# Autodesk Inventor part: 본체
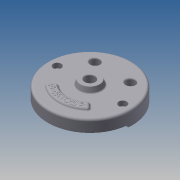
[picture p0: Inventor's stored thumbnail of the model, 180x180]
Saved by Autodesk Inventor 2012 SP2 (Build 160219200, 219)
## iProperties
Created: 2015-05
Part Number: 본체
Material: 알루미늄-6061
Document SubType Name: Modeling
Designer: Administrator
Density: 2.71 g/cm^3
Mass: 1082.43 g
Surface Area: 1039.74 cm^2
Volume: 399.421 cm^3
Author: Administrator
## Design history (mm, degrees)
sketch "스케치1"
  geometry: C1 r 95 at (0, 0); 1 further point
  constraints: 1 centre point, 1 coincident
  dimensions: "d0" = 190 diameter of C1
extrude "돌출1" new body sketch "스케치1" distance "d1" = 32; taper "d2" = 0 deg
sketch "스케치2"
  geometry: C1 r 95 at (0, 0) reference; C2 r 25 at (0, 0)
  constraints: 1 centre point, 1 coincident
  dimensions: "d3" = 50 diameter of C2
extrude "돌출2" join sketch "스케치2" distance "d4" = 12; taper "d5" = 0 deg
sketch "스케치3"
  geometry: L1 (0, 0)-(0, 49.604); L2 (-25, 32)-(-25, 44) reference; L3 (-25, 44)-(25, 44) reference; L4 (-25, 32)-(-21.785, 44); L5 (-95, 32)-(95, 32) reference
  constraints: 4 end point, 1 point on line, 1 vertical
  dimensions: "d6" = 105 deg angle of L5 L4
revolve "회전1" sketch "스케치3" stored, may be unused: angle "d7" = 90 deg
sketch "스케치4"
  geometry: L1 (0, 0)-(-94.638, -8.28); L2 (0, 0)-(94.638, -8.28); L3 (0, 0)-(-95, 0); L4 (0, 0)-(95, 0); A1 r 95 centre (0, 0) between (-94.638, -8.28) and (94.638, -8.28) reference
  constraints: 8 end point, 4 point on circle, 1 collinear, 1 horizontal
  dimensions: "d8" = 5 deg angle of L1 L3; "d9" = 5 deg angle of L2 L4
extrude "돌출3" cut sketch "스케치4" distance "d10" = 5; taper "d11" = 0 deg
sketch "스케치5"
  geometry: L1 (-89.196, 12)-(-40.249, 12); L2 (40.249, 12)-(89.196, 12); A1 r 95 centre (0, 0) between (94.638, -8.28) and (-94.638, -8.28) reference; A2 r 90 centre (0, 0) between (89.196, 12) and (-89.196, 12); A3 r 42 centre (0, 0) between (40.249, 12) and (-40.249, 12); 1 further point
  constraints: 4 end point, 4 point on circle, 2 centre point, 2 coincident, 2 horizontal, 1 collinear
  dimensions: "d12" = 180 diameter of A2; "d14" = 84 diameter of A3; "d15" = 12 distance from line of L1 point (0, 0)
extrude "돌출4" cut sketch "스케치5" distance "d16" = 25; taper "d17" = 0 deg
sketch "스케치6"
  geometry: L1 (-40.249, 12)-(-89.196, 12) reference; L2 (89.196, 12)-(40.249, 12) reference; L3 (-89.196, 12)-(-40.249, 12); L4 (89.196, 12)-(40.249, 12); A1 r 95 centre (0, 0) between (94.638, -8.28) and (-94.638, -8.28) reference; A2 r 90 centre (0, 0) between (-89.196, 12) and (89.196, 12); A3 r 42 centre (0, 0) between (40.249, 12) and (-40.249, 12)
  constraints: 4 end point, 4 point on circle, 2 centre point, 2 coincident, 2 collinear
extrude "돌출5" cut sketch "스케치6" distance "d19" = 18; taper "d20" = 0 deg
sketch "스케치7"
  geometry: C1 r 35 at (0, 0); A1 r 42 centre (0, 0) between (40.249, 12) and (-40.249, 12) reference
  constraints: 1 centre point, 1 coincident
  dimensions: "d21" = 70 diameter of C1
extrude "돌출6" join sketch "스케치7" distance "d22" = 10; taper "d23" = 0 deg
sketch "스케치8"
  geometry: L1 (-89.196, 12)-(-40.249, 12) reference; L2 (-59, -19)-(59, -19); L3 (-59, -19)-(-59, -14); L4 (-41, -19)-(-41, -14); L5 (41, -19)-(41, -14); L6 (59, -19)-(59, -14); C1 r 35 at (0, 0) reference; A1 r 59 centre (0, -19) between (-59, -19) and (59, -19); A2 r 41 centre (0, -19) between (-41, -19) and (41, -19); A3 r 9 centre (-50, -14) between (-41, -14) and (-59, -14); A4 r 9 centre (50, -14) between (59, -14) and (41, -14); 1 further point
  constraints: 10 end point, 8 point on circle, 8 tangent, 7 parallel, 4 centre point, 2 coincident, 2 point on line, 1 midpoint, 1 perpendicular, 1 vertical alignment
  dimensions: "d24" = 118 diameter of A1; "d25" = 19 distance of A1.centre C1.centre; "d26" = 82 diameter of A2; "d27" = 5 distance of L2.start L3.end
extrude "돌출7" cut sketch "스케치8" distance "d28" = 7; taper "d29" = 0 deg
chamfer "모따기1" distance "d30" = 1; stored, may be unused: second distance "d31" = 2, angle "d32" = 45 deg
sketch "스케치9"
  geometry: C1 r 35 at (0, 0) reference; C2 r 25 at (0, 0)
  constraints: 1 centre point, 1 coincident
  dimensions: "d33" = 50 diameter of C2
extrude "돌출8" cut sketch "스케치9" distance "d34" = 15; taper "d35" = 0 deg
sketch "스케치10"
  geometry: C1 r 25 at (0, 0) reference; C2 r 11.5 at (0, 0)
  constraints: 1 centre point, 1 coincident
  dimensions: "d36" = 23 diameter of C2
extrude "돌출9" cut sketch "스케치10" stored distance "d37" = 15; taper "d38" = 0 deg
chamfer "모따기2" distance "d39" = 1; stored, may be unused: second distance "d40" = 2, angle "d41" = 45 deg
chamfer "모따기3" distance "d42" = 1; stored, may be unused: second distance "d43" = 2, angle "d44" = 45 deg
fillet "모깎기1" dims "d45" = 10
sketch "스케치11"
  geometry: L1 (35, 8)-(-35, 8) reference; L2 (35, 18)-(35, 8) reference; L3 (35, 18)-(33.237, 8); L4 (42, 18)-(17.769, 18) reference; L5 (0, -8.8)-(0, 52.8) reference; 1 further point
  constraints: 2 end point, 1 point on line
  dimensions: "d46" = 100 deg angle of L4 L3
revolve "회전2" sketch "스케치11" stored, may be unused: angle "d47" = 90 deg
sketch "스케치12"
  geometry: C1 r 15 at (-40, 52); C2 r 15 at (40, 52); C3 r 95 at (0, 0) reference; A1 r 90 centre (0, 0) between (86.53, 24.75) and (-86.53, 24.75) reference
  constraints: 2 centre point, 1 horizontal alignment
  dimensions: "d48" = 30 diameter of C1; "d49" = 30 diameter of C2; "d51" = 80 distance of C2.centre C1.centre; "d52" = 52 vertical distance of C1.centre A1.centre; "d53" = 40 horizontal distance of C3.centre C1.centre
extrude "돌출10" join sketch "스케치12" distance "d54" = 25; taper "d55" = 0 deg
hole "구멍1" diameter "d58" = 20; stored, may be unused: countersink angle "d62" = 90 deg, drill point angle "d64" = 118 deg; dims "d56" = 10, "d57" = 10, "d59" = 6, "d60" = 4, "d61" = 2, "d63" = 8
hole "구멍2" diameter "d67" = 20; stored, may be unused: countersink angle "d71" = 90 deg, drill point angle "d73" = 118 deg; dims "d65" = 10, "d66" = 10, "d68" = 6, "d69" = 4, "d70" = 2, "d72" = 8
sketch "스케치13"
  geometry: C1 r 9 at (-74, 0); C2 r 9 at (74, 0); A1 r 90 centre (0, 0) between (-86.53, 24.75) and (86.53, 24.75) reference
  constraints: 2 centre point, 2 horizontal alignment
  dimensions: "d74" = 18 diameter of C1; "d75" = 18 diameter of C2; "d76" = 74 distance of C1.centre A1.centre; "d77" = 148 distance of C2.centre C1.centre
extrude "돌출11" join sketch "스케치13" distance "d78" = 18; taper "d79" = 0 deg
hole "구멍3" diameter "d82" = 11; stored, may be unused: countersink angle "d86" = 90 deg, drill point angle "d88" = 118 deg; dims "d80" = 10, "d81" = 10, "d83" = 6, "d84" = 4, "d85" = 2, "d87" = 8
hole "구멍4" diameter "d91" = 11; stored, may be unused: countersink angle "d95" = 90 deg, drill point angle "d97" = 118 deg; dims "d89" = 10, "d90" = 10, "d92" = 6, "d93" = 4, "d94" = 2, "d96" = 8
sketch "스케치14"
  geometry: C1 r 5.5 at (-74, 0) reference; C2 r 5.5 at (74, 0) reference; C3 r 9 at (-74, 0); C4 r 9 at (74, 0)
  constraints: 2 centre point, 2 coincident
  dimensions: "d98" = 18 diameter of C3; "d99" = 18 diameter of C4
extrude "돌출12" cut sketch "스케치14" distance "d100" = 11; taper "d101" = 0 deg
sketch "스케치15"
  geometry: L1 (0, 0)-(-50.912, -50.912); L2 (0, 0)-(50.912, -50.912); L3 (0, 0)-(0, -72); L4 (-36.062, -36.062)-(-50.912, -50.912); L5 (36.062, -36.062)-(50.912, -50.912); C1 r 95 at (0, 0) reference; A1 r 51 centre (0, 0) between (-36.062, -36.062) and (36.062, -36.062); A2 r 72 centre (0, 0) between (-50.912, -50.912) and (50.912, -50.912)
  constraints: 10 end point, 5 point on circle, 2 centre point, 2 coincident, 2 collinear, 2 point on line, 1 perpendicular, 1 vertical
  dimensions: "d103" = 102 diameter of A1; "d104" = 45 deg angle of L3 L1; "d105" = 72 radius of A2
extrude "돌출13" join sketch "스케치15" distance "d106" = 5; taper "d107" = 0 deg
fillet "모깎기2" dims "d108" = 5
fillet "모깎기3" dims "d109" = 5
fillet "모깎기4" dims "d110" = 3
fillet "모깎기5" dims "d111" = 3, "d125" = 5
fillet "모깎기6" dims "d112" = 1
fillet "모깎기7" dims "d113" = 3
fillet "모깎기8" dims "d114" = 3
fillet "모깎기9" dims "d115" = 3
sketch "스케치16"
  geometry: L1 (-6, 13.748)-(-6, -13.748); L2 (6, 13.748)-(6, -13.748); L3 (66.252, 6)-(93.748, 6); L4 (66.252, -6)-(93.748, -6); C1 r 10 at (80, 0) reference; A1 r 15 centre (0, 0) between (-6, 13.748) and (6, 13.748) reference; A2 r 15 centre (80, 0) between (66.252, 6) and (93.748, 6) reference; 1 further point
  constraints: 8 end point, 8 point on circle, 4 parallel, 1 perpendicular, 1 vertical
  dimensions: "d116" = 12 distance between parallel lines of L2 L1; "d117" = 12 distance between parallel lines of L4 L3
extrude "돌출14" cut sketch "스케치16" distance "d118" = 3; taper "d119" = 0 deg
sketch "스케치17"
  geometry: C1 r 68 at (0, 0); A1 r 56 centre (0, 0) between (-35.904, -42.975) and (35.904, -42.975) reference
  constraints: 1 centre point, 1 coincident, 1 other
  dimensions: "d120" = 136 diameter of C1
feature "엠보싱1" sketch "스케치17" dims "d0" = 190, "d121" = 0.5, "d122" = 0
fillet "모깎기10" dims "d123" = 3
fillet "모깎기11" dims "d124" = 3
fillet "모깎기12" dims "d126" = 0.3
node "솔리드1"
other parameters: "d13" = 12, "d102" = 144
